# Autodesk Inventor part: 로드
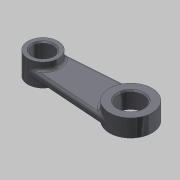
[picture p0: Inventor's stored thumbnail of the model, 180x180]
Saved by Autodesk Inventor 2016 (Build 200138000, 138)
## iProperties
Created: 2015-10
Part Number: 로드
Document SubType Name: Modeling
Designer: mdu
Density: 7.86 g/cm^3
Material: 강철, 연강
Mass: 20.3759 g
Surface Area: 22.2266 cm^2
Volume: 2.59236 cm^3
Appearance: 강철 - 광택
Author: mdu
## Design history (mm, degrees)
sketch "스케치1"
  geometry: L1 (13.821, 5.985)-(48.643, 8.478); L2 (48.643, -8.478)-(13.821, -5.985); C1 r 4 at (14.25, 0) reference; A1 r 6 centre (14.25, 0) between (13.821, 5.985) and (13.821, -5.985); A2 r 8.5 centre (49.25, 0) between (48.643, 8.478) and (48.643, -8.478); 1 further point
  constraints: 4 end point, 4 point on circle, 4 tangent, 2 centre point, 1 coincident, 1 horizontal alignment
  dimensions: "d0" = 12 diameter of A1; "d1" = 35 distance of A2.centre A1.centre; "d2" = 17 diameter of A2
  node "참조1"
extrude "돌출1" new body sketch "스케치1" distance "d3" = 9; taper "d4" = 0 deg
node "작업 평면1"
node "작업 평면2"
extrude "돌출2" join sketch "스케치1" stored distance "d7" = 10; taper "d8" = 0 deg
node "작업 평면3"
extrude "돌출3" join sketch "스케치1" stored distance "d10" = 10; taper "d11" = 0 deg
hole "구멍1" diameter "d14" = 10; stored, may be unused: countersink angle "d18" = 90 deg, drill point angle "d20" = 118 deg; dims "d12" = 10, "d13" = 10, "d15" = 6, "d16" = 4, "d17" = 2, "d19" = 8
fillet "모깎기1" dims "d21" = 1
chamfer "모따기1" distance "d22" = 0.5; stored, may be unused: second distance "d23" = 2, angle "d24" = 45 deg
chamfer "모따기2" distance "d25" = 0.5; stored, may be unused: second distance "d26" = 2, angle "d27" = 45 deg
node "솔리드1"
other parameters: "d5" = -6, "d6" = -3, "d9" = -4
